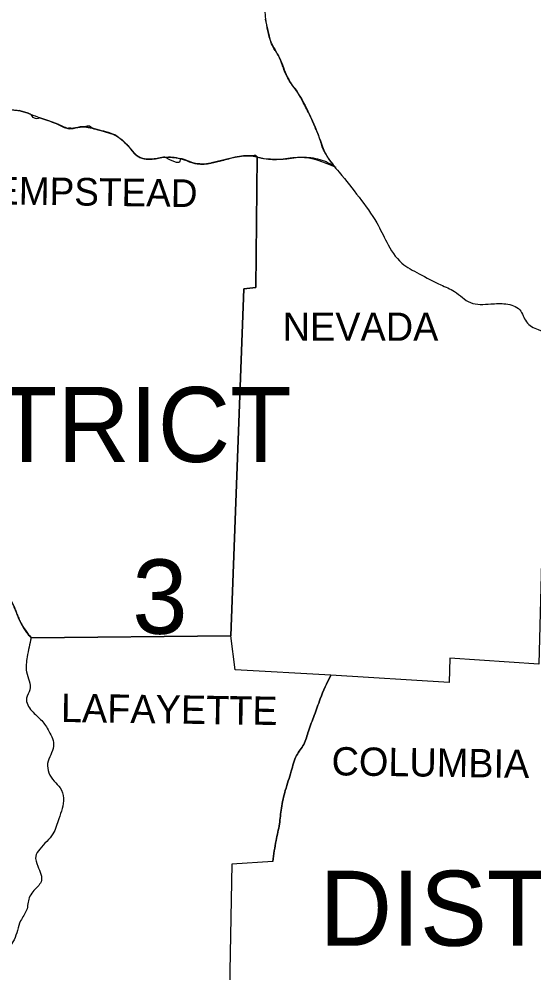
# Model space of a CAD drawing. Extents: x -12863 to 18921, y -8840 to 11152.
# Drawn here: x 11783 to 12548, y 5265 to 6683 of the extents above; entities that cross this region are included whole.
import ezdxf

# ---------------------------------------------------------------- set-up
doc = ezdxf.new("R2010")
doc.units = 0
for name, color, linetype in [('Level 1', 7, 'Continuous'), ('Level 2', 7, 'Continuous'), ('Level 3', 7, 'Continuous'), ('Level 48', 7, 'Continuous')]:
    doc.layers.add(name, color=color, linetype=linetype)

msp = doc.modelspace()

# ---------------------------------------------------------------- linework, layer by layer
at = {"layer": 'Level 1'}
for points in [[(12136.685074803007, 6478.611953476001), (12134.728261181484, 6283.908996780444), (12117.116938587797, 6281.952183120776), (12097.548802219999, 5766.331790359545)], [(12568.162481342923, 6217.377333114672), (12555.443192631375, 5724.260297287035), (12423.358272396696, 5733.06595852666), (12422.379865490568, 5696.86490635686), (12246.266638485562, 5707.62738140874)], [(12246.266638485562, 5707.62738140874), (12104.397649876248, 5715.454635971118), (12097.548802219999, 5766.331790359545), (11801.09153644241, 5763.396570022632)], [(12160.166838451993, 5430.73825199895), (12099.50561584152, 5426.824624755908), (12092.656768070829, 5082.425425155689)]]:
    msp.add_lwpolyline(points, dxfattribs=at)
for points in [[(12084.829513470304, 6880.7371554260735), (12100.48402259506, 6870.953087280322), (12119.073752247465, 6862.147425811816), (12128.857820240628, 6847.471323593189), (12132.771447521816, 6824.967966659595), (12139.620295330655, 6800.507796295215), (12141.577108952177, 6775.069219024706), (12135.706668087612, 6761.371523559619), (12143.533922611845, 6730.062505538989), (12146.469142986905, 6708.537555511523), (12149.404363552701, 6683.098978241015), (12157.231618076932, 6648.854739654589), (12169.950906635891, 6625.37297604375), (12181.691788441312, 6596.9991783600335), (12201.25992480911, 6566.668566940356), (12217.892840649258, 6533.402735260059), (12225.720095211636, 6515.791412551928), (12240.396197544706, 6479.590360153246), (12258.985927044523, 6455.130189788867), (12288.33813159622, 6417.950730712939), (12314.755115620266, 6379.792864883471), (12329.431217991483, 6351.419067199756), (12351.934574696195, 6320.110048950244), (12377.37315200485, 6304.455539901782), (12409.660576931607, 6287.82262409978), (12430.207120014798, 6278.038555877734), (12453.688883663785, 6261.405640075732), (12484.019494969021, 6259.448826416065), (12506.522851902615, 6259.448826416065), (12527.069394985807, 6250.643164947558), (12536.853463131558, 6233.031842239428), (12554.464785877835, 6221.2909603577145), (12568.162481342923, 6217.377333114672)], [(11684.224975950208, 6556.249495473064), (11725.754211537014, 6552.970871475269), (11759.998450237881, 6549.0572441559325), (11786.41543426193, 6546.122023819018), (11813.810825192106, 6536.337955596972), (11838.270995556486, 6527.532294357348), (11853.925504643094, 6520.683446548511), (11880.342488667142, 6522.640260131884), (11902.845845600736, 6517.748226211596), (11928.284422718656, 6508.942564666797), (11946.874152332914, 6492.309648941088), (11958.61503417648, 6479.590360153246), (11981.118390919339, 6474.698326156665), (11999.708120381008, 6477.633546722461), (12022.211477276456, 6475.676733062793), (12047.650054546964, 6467.849478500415), (12068.196597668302, 6468.827885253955), (12084.829513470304, 6472.741512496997), (12104.397649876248, 6477.633546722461), (12128.857820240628, 6479.590360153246), (12147.447549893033, 6475.676733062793), (12171.907720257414, 6474.698326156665), (12200.281517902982, 6477.633546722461), (12253.57048874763, 6462.8310547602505)], [(11400.923148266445, 5874.934947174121), (11435.167386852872, 5889.611049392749), (11449.843489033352, 5884.719015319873), (11462.5627777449, 5871.999726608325), (11477.238879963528, 5871.999726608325), (11485.066134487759, 5883.740608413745), (11499.742236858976, 5884.719015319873), (11511.483118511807, 5883.740608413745), (11524.202407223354, 5891.567862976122), (11534.964882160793, 5896.459897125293), (11549.64098453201, 5901.351931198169), (11560.403459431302, 5905.2655584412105), (11570.1875276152, 5916.028033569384), (11587.798850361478, 5924.833694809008), (11608.345393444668, 5931.682542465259), (11614.215834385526, 5941.466610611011), (11623.999902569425, 5945.380237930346), (11643.568038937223, 5944.401831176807), (11656.287327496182, 5950.272272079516), (11667.049802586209, 5945.380237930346), (11676.833870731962, 5938.531390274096), (11678.79068439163, 5913.092813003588), (11686.617938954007, 5899.395117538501), (11698.358820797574, 5874.934947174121), (11714.99173656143, 5862.215658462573), (11730.646245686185, 5849.496369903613), (11736.516686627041, 5841.669115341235), (11753.14960246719, 5826.993013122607), (11767.82570480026, 5822.100978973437), (11774.67455245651, 5811.338503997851), (11785.437027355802, 5785.899926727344), (11801.09153644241, 5763.396570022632)], [(11801.09153644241, 5763.396570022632), (11795.221095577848, 5735.0227721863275), (11794.242688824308, 5712.519415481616), (11799.134722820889, 5686.102431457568), (11794.242688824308, 5673.38314274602), (11802.069943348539, 5654.793413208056), (11816.746045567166, 5640.117311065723), (11827.508520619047, 5624.4628019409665), (11834.357368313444, 5601.959445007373), (11825.551706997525, 5576.520867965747), (11835.335775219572, 5550.103883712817), (11844.141436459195, 5540.319815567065), (11849.033470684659, 5524.665306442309), (11842.184622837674, 5494.334695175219), (11833.378961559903, 5471.831338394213), (11813.810825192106, 5449.327981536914), (11807.940384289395, 5438.565506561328), (11810.87560462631, 5423.889404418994), (11815.767638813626, 5400.40764073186), (11810.87560462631, 5393.558792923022), (11798.156316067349, 5376.92587712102), (11794.242688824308, 5358.33614765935), (11785.437027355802, 5342.681638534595), (11775.652959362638, 5314.30784069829), (11762.933670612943, 5290.826077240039), (11760.976856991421, 5264.409093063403), (11741.408720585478, 5264.409093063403), (11718.905363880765, 5264.409093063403), (11698.358820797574, 5249.7329908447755), (11679.76909114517, 5248.754583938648), (11657.26573440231, 5239.948922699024), (11643.568038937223, 5221.359193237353), (11638.676004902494, 5200.812649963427), (11632.805563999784, 5181.2445135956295), (11638.676004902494, 5147.978681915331), (11647.481666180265, 5124.496918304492), (11654.330513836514, 5105.90718861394), (11666.071395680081, 5075.57657734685)], [(12160.166838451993, 5430.73825199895), (12165.05887263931, 5462.047270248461), (12169.950906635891, 5486.5074406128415), (12172.886127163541, 5509.989204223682), (12178.756568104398, 5536.406188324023), (12187.562229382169, 5564.779986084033), (12195.3894839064, 5588.2617496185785), (12206.15195880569, 5604.894665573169), (12213.000806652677, 5624.4628019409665), (12221.806467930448, 5647.944565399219), (12230.612129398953, 5672.40473599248), (12246.266638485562, 5707.62738140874)]]:
    msp.add_spline(points, degree=3, dxfattribs=at)
at = {"layer": 'Level 48'}
for p, q in [((12157.231618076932, 6648.854739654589), (12149.430175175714, 6682.890797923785)), ((11786.41543426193, 6546.122023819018), (11783.151815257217, 6546.813521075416)), ((11788.004384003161, 6545.716124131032), (11786.415434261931, 6546.122023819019)), ((11793.416260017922, 6544.079103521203), (11788.004384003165, 6545.716124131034)), ((11827.192270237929, 6531.523843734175), (11813.810825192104, 6536.337955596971)), ((11838.270995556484, 6527.532294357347), (11827.192270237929, 6531.523843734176)), ((11840.671905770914, 6526.582323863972), (11838.270995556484, 6527.532294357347)), ((11842.207581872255, 6525.900785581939), (11840.671905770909, 6526.5823238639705)), ((11849.923944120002, 6522.24184290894), (11846.05493396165, 6524.059128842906)), ((11877.58567751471, 6522.846575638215), (11873.746675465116, 6522.525669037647)), ((11880.342488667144, 6522.640260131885), (11877.58567751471, 6522.846575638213)), ((11867.061234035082, 6521.133758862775), (11860.412173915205, 6520.005895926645)), ((11902.845845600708, 6517.748226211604), (11891.619067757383, 6520.505593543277)), ((11915.693227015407, 6514.32547525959), (11908.949037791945, 6516.1663243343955)), ((11915.881764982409, 6514.272311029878), (11915.693227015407, 6514.32547525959)), ((11920.119255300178, 6512.85322364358), (11915.881764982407, 6514.272311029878)), ((11923.811730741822, 6511.325090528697), (11922.207173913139, 6512.02970897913)), ((11925.282433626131, 6510.615522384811), (11923.811730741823, 6511.325090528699)), ((11928.284422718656, 6508.942564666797), (11925.282433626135, 6510.615522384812)), ((11938.083539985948, 6501.103951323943), (11928.284422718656, 6508.942564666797)), ((11946.874152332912, 6492.309648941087), (11938.08353998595, 6501.103951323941)), ((11951.293284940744, 6487.122491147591), (11949.69766156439, 6489.164088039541)), ((11952.27300157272, 6485.863031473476), (11951.293284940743, 6487.122491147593)), ((11958.61503417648, 6479.590360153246), (11952.273001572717, 6485.863031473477)), ((12116.589936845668, 6479.522672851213), (12104.397649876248, 6477.633546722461)), ((12120.822924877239, 6479.738221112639), (12116.589936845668, 6479.5226728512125)), ((12128.857820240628, 6479.590360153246), (12122.752286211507, 6479.7681118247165)), ((11964.83291060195, 6476.395905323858), (11964.097617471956, 6476.667742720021)), ((11969.719617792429, 6475.1508068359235), (11964.832910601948, 6476.395905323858)), ((11975.189498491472, 6474.637350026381), (11969.719617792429, 6475.150806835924)), ((11981.118390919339, 6474.698326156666), (11975.189498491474, 6474.637350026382)), ((11983.913866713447, 6474.957334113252), (11981.118390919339, 6474.698326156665)), ((11985.763499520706, 6475.259851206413), (11983.913866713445, 6474.957334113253)), ((11990.408432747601, 6476.256197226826), (11985.763499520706, 6475.259851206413)), ((11995.055777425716, 6477.207412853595), (11990.408432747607, 6476.256197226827)), ((11997.795583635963, 6477.552759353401), (11995.055777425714, 6477.207412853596)), ((11999.708120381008, 6477.633546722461), (11997.79558363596, 6477.552759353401)), ((12025.463872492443, 6474.942097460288), (12022.211477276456, 6475.676733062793)), ((12028.6646643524, 6473.946619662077), (12025.463872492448, 6474.942097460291)), ((12034.955247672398, 6471.560421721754), (12028.664664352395, 6473.946619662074)), ((12041.233590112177, 6469.275565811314), (12034.955247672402, 6471.560421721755)), ((12045.519318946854, 6468.176389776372), (12041.23359011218, 6469.275565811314)), ((12047.650054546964, 6467.849478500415), (12045.519318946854, 6468.17638977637)), ((12068.196597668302, 6468.827885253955), (12057.941363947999, 6467.4799135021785)), ((12136.680049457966, 6478.111931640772), (12136.559396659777, 6478.144430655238)), ((12136.685074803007, 6478.611953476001), (12136.680049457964, 6478.11193164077)), ((11801.09153644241, 5763.396570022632), (12097.548802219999, 5766.331790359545))]:
    msp.add_line(p, q, dxfattribs=at)
for points in [[(12097.548802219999, 5766.331790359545), (12117.116938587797, 6281.952183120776), (12134.728261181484, 6283.908996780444), (12136.680049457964, 6478.111931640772)], [(12136.559396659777, 6478.144430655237), (12136.685074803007, 6478.611953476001)], [(12555.346192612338, 5724.266763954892), (12423.358272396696, 5733.06595852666), (12422.379865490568, 5696.86490635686), (12246.266638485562, 5707.62738140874)], [(12160.16683845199, 5430.738251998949), (12099.50561584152, 5426.824624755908), (12092.656768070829, 5082.425425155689)]]:
    msp.add_lwpolyline(points, dxfattribs=at)
for points in [[(12084.829513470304, 6880.7371554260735), (12100.48402259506, 6870.953087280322), (12119.073752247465, 6862.147425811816), (12128.857820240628, 6847.471323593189), (12132.771447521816, 6824.967966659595), (12139.620295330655, 6800.507796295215), (12141.577108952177, 6775.069219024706), (12135.706668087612, 6761.371523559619), (12143.533922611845, 6730.062505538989), (12146.469142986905, 6708.537555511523), (12149.404363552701, 6683.098978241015), (12157.231618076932, 6648.854739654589), (12169.950906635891, 6625.37297604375), (12181.691788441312, 6596.9991783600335), (12201.25992480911, 6566.668566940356), (12217.892840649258, 6533.402735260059), (12225.720095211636, 6515.791412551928), (12240.396197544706, 6479.590360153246), (12258.985927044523, 6455.130189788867), (12288.33813159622, 6417.950730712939), (12314.755115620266, 6379.792864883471), (12329.431217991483, 6351.419067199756), (12351.934574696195, 6320.110048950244), (12377.37315200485, 6304.455539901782), (12409.660576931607, 6287.82262409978), (12430.207120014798, 6278.038555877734), (12453.688883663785, 6261.405640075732), (12484.019494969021, 6259.448826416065), (12506.522851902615, 6259.448826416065), (12527.069394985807, 6250.643164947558), (12536.853463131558, 6233.031842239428), (12554.464785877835, 6221.2909603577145), (12568.162481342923, 6217.377333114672)], [(11684.240166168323, 6556.248841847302), (11725.754211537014, 6552.970871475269), (11759.998450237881, 6549.0572441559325), (11773.25629404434, 6548.0059087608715), (11779.86753077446, 6547.330862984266), (11783.151815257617, 6546.8135210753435), (11786.41543426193, 6546.122023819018), (11793.416260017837, 6544.079103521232), (11800.2496263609, 6541.592829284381), (11813.810825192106, 6536.337955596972), (11838.270995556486, 6527.532294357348), (11842.207581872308, 6525.900785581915), (11846.054933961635, 6524.059128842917), (11849.923944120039, 6522.241842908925), (11853.925504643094, 6520.683446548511), (11860.412173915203, 6520.005895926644), (11867.061234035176, 6521.133758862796), (11873.746675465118, 6522.525669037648), (11880.342488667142, 6522.640260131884), (11891.619067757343, 6520.505593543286), (11902.845845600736, 6517.748226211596), (11915.881764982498, 6514.272311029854), (11922.20717391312, 6512.029708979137), (11925.282433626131, 6510.615522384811), (11928.284422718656, 6508.942564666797), (11938.083539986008, 6501.103951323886), (11946.874152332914, 6492.309648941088), (11949.697661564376, 6489.164088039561), (11952.273001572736, 6485.863031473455), (11958.61503417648, 6479.590360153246), (11964.097617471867, 6476.667742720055), (11969.71961779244, 6475.150806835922), (11981.118390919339, 6474.698326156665), (11985.763499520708, 6475.259851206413), (11990.408432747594, 6476.256197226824), (11995.055777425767, 6477.207412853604), (11999.708120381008, 6477.633546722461), (12022.211477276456, 6475.676733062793), (12028.664664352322, 6473.946619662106), (12034.955247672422, 6471.560421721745), (12041.233590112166, 6469.275565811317), (12047.650054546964, 6467.849478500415), (12052.76136923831, 6467.464625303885), (12057.941363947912, 6467.479913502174), (12068.196597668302, 6468.827885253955), (12084.829513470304, 6472.741512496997), (12104.397649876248, 6477.633546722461), (12116.589936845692, 6479.522672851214), (12122.752286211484, 6479.7681118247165), (12128.857820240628, 6479.590360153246), (12136.559396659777, 6478.144430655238)], [(11800.249626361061, 6541.592829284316), (11800.2496263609, 6541.592829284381), (11793.41626001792, 6544.079103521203)], [(11813.810825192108, 6536.337955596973), (11813.810825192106, 6536.337955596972), (11800.249626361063, 6541.592829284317)], [(11846.054933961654, 6524.05912884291), (11846.054933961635, 6524.059128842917), (11842.207581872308, 6525.900785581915), (11842.207581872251, 6525.900785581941)], [(11853.925504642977, 6520.683446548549), (11849.923944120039, 6522.241842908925), (11849.92394412, 6522.241842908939)], [(11873.74667546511, 6522.525669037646), (11867.061234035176, 6521.133758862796), (11867.061234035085, 6521.133758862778)], [(11891.61906775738, 6520.5055935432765), (11880.342488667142, 6522.640260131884), (11880.34248866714, 6522.640260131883)], [(11854.710488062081, 6520.450682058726), (11853.925504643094, 6520.683446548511), (11853.925504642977, 6520.68344654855)], [(11860.412173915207, 6520.005895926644), (11860.412173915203, 6520.005895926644), (11854.710488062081, 6520.450682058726)], [(11908.949037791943, 6516.1663243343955), (11902.845845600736, 6517.748226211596), (11902.845845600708, 6517.748226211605)], [(11922.207173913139, 6512.029708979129), (11922.20717391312, 6512.029708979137), (11920.11925530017, 6512.8532236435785)], [(11949.697661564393, 6489.164088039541), (11949.697661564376, 6489.164088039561), (11946.874152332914, 6492.309648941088)], [(11964.097617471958, 6476.667742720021), (11964.097617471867, 6476.667742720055), (11958.61503417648, 6479.590360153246)], [(12122.752286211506, 6479.7681118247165), (12122.752286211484, 6479.7681118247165), (12120.82292487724, 6479.738221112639)], [(12136.559396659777, 6478.144430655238), (12128.857820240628, 6479.590360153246), (12128.857820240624, 6479.590360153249)], [(12022.211477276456, 6475.676733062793), (11999.708120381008, 6477.633546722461), (11999.70812038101, 6477.633546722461)], [(12136.680049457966, 6478.111931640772), (12142.032311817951, 6476.664765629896), (12147.447549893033, 6475.676733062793), (12159.670621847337, 6474.882897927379), (12171.907720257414, 6474.698326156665), (12179.012567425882, 6475.141780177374), (12186.105670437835, 6476.095226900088), (12193.193247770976, 6477.084028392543), (12200.281517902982, 6477.633546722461), (12213.505043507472, 6477.266756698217), (12226.593825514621, 6475.211607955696), (12239.385293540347, 6470.997306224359), (12251.716877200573, 6464.15305723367)], [(11401.970630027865, 5875.762733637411), (11410.038158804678, 5881.300332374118), (11418.321702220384, 5885.515487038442), (11426.728898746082, 5888.316343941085), (11430.950003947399, 5889.1577064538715), (11435.167386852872, 5889.611049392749), (11438.82118587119, 5889.341318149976), (11442.520433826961, 5888.264884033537), (11446.212183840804, 5886.638524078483), (11449.843489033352, 5884.719015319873), (11453.491548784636, 5881.84193745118), (11456.464932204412, 5878.289693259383), (11459.30741621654, 5874.772287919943), (11462.5627777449, 5871.999726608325), (11469.87758880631, 5870.38422223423), (11473.804964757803, 5870.8442190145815), (11477.238879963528, 5871.999726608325), (11479.435402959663, 5874.5058688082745), (11480.846005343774, 5878.25179409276), (11482.409858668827, 5881.806906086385), (11485.066134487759, 5883.740608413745), (11488.73326028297, 5884.283980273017), (11492.403641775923, 5884.597624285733), (11496.074295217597, 5884.727362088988), (11499.742236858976, 5884.719015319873), (11502.67961757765, 5884.3910291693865), (11505.617538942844, 5883.812605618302), (11510.018935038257, 5883.479551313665), (11510.751265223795, 5883.578457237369), (11511.483118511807, 5883.740608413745), (11514.928437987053, 5885.222733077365), (11518.020976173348, 5887.350551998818), (11521.024407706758, 5889.630212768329), (11524.202407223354, 5891.567862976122), (11526.8541714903, 5892.860173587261), (11529.516322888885, 5894.153550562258), (11534.964882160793, 5896.459897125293), (11549.64098453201, 5901.351931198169), (11560.403459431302, 5905.2655584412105), (11563.249118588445, 5907.3571858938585), (11565.427322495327, 5910.381345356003), (11567.539611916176, 5913.538230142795), (11570.1875276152, 5916.028033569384), (11578.855900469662, 5920.722356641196), (11587.798850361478, 5924.833694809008), (11592.877181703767, 5926.688179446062), (11598.111097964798, 5928.177223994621), (11603.325526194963, 5929.706715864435), (11608.345393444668, 5931.682542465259), (11610.238379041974, 5933.590616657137), (11611.31993120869, 5936.356302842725), (11612.381824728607, 5939.2311258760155), (11614.215834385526, 5941.466610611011), (11616.547921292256, 5942.866234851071), (11618.955985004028, 5943.986147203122), (11623.999902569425, 5945.380237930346), (11628.937732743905, 5945.560966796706), (11633.968008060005, 5945.0118671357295), (11638.906264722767, 5944.402351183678), (11643.568038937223, 5944.401831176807), (11646.752995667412, 5945.663915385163), (11649.930844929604, 5947.879706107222), (11653.107113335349, 5949.824169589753), (11656.287327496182, 5950.272272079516), (11661.667218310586, 5948.295230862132), (11667.049802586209, 5945.380237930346), (11672.27531092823, 5942.386166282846), (11674.661302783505, 5940.6674813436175), (11675.777182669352, 5939.664250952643), (11676.833870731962, 5938.531390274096), (11679.049497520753, 5932.707550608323), (11678.525243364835, 5926.034450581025), (11677.644506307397, 5919.250176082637), (11678.79068439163, 5913.092813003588), (11680.699467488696, 5909.655069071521), (11682.706384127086, 5906.245452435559), (11684.712264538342, 5902.835092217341), (11686.617938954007, 5899.395117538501), (11689.308010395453, 5893.147772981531), (11691.635519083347, 5886.65524926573), (11696.172899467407, 5877.550657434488), (11697.20938611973, 5876.207489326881), (11698.358820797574, 5874.934947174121), (11702.291174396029, 5871.414373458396), (11706.49590851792, 5868.298034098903), (11710.790327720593, 5865.32032909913), (11714.99173656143, 5862.215658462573), (11722.882252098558, 5855.938539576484), (11730.646245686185, 5849.496369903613), (11732.29759060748, 5847.718360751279), (11733.687404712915, 5845.70455215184), (11735.024249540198, 5843.629838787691), (11736.516686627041, 5841.669115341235), (11744.465728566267, 5833.874596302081), (11748.743274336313, 5830.341582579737), (11753.14960246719, 5826.993013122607), (11756.673031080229, 5825.487299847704), (11760.663262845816, 5824.851298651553), (11764.565690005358, 5824.0631461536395), (11766.310661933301, 5823.292680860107), (11767.82570480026, 5822.100978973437), (11771.692481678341, 5816.977172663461), (11774.67455245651, 5811.338503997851), (11777.478317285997, 5805.012819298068), (11780.04657591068, 5798.624648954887), (11782.619441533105, 5792.23376181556), (11785.437027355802, 5785.899926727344), (11788.535932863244, 5779.82862433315), (11792.008155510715, 5774.072396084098), (11796.10844135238, 5768.604093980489), (11798.473716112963, 5765.969431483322), (11801.09153644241, 5763.396570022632)], [(12246.266638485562, 5707.62738140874), (12230.612129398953, 5672.40473599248), (12221.806467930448, 5647.944565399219), (12213.000806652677, 5624.4628019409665), (12206.15195880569, 5604.894665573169), (12195.3894839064, 5588.2617496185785), (12187.562229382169, 5564.779986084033), (12178.756568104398, 5536.406188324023), (12172.886127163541, 5509.989204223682), (12169.950906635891, 5486.5074406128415), (12165.05887263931, 5462.047270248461), (12160.166838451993, 5430.73825199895)]]:
    msp.add_spline(points, degree=3, dxfattribs=at)
for points, degree in [([(12181.691788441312, 6596.9991783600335), (12176.96471033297, 6606.0694115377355), (12174.23627494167, 6616.12881380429), (12169.950906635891, 6625.37297604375), (12166.22400291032, 6633.412449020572), (12160.422905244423, 6640.426176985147), (12157.231618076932, 6648.854739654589)], 3), ([(12217.892840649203, 6533.402735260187), (12212.734125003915, 6544.685333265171), (12207.044868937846, 6555.706124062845), (12201.25992480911, 6566.668566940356), (12195.6456416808, 6577.30760799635), (12187.248319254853, 6586.3374061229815), (12181.691788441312, 6596.9991783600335), (12181.691788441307, 6596.9991783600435), (12181.691788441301, 6596.999178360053), (12181.691788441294, 6596.999178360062)], 3), ([(12227.87013113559, 6510.475942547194), (12227.196538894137, 6512.266966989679), (12226.487306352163, 6514.042122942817), (12225.720095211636, 6515.791412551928), (12223.140703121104, 6521.67258859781), (12220.565991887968, 6527.556301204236), (12217.892840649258, 6533.402735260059)], 3), ([(12240.396197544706, 6479.590360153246), (12234.498346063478, 6489.111822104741), (12231.78669903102, 6500.0621218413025), (12227.87013113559, 6510.475942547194)], 2), ([(12251.716877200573, 6464.15305723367), (12247.709244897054, 6469.107954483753), (12243.781622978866, 6474.124946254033), (12240.396197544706, 6479.590360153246)], 2), ([(12057.941363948, 6467.479913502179), (12057.941363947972, 6467.479913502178), (12057.94136394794, 6467.479913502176), (12057.941363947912, 6467.479913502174), (12056.216686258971, 6467.377723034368), (12054.486629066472, 6467.4059826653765), (12052.76136923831, 6467.464625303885), (12051.054172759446, 6467.522653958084), (12049.351252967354, 6467.628036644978), (12047.650054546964, 6467.849478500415)], 3), ([(12084.829513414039, 6472.741512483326), (12079.294531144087, 6471.396634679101), (12073.76944445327, 6470.078557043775), (12068.196597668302, 6468.827885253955)], 2), ([(12104.397649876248, 6477.633546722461), (12097.847674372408, 6476.052231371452), (12091.363492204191, 6474.329282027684), (12084.829513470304, 6472.741512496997), (12084.82951345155, 6472.74151249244), (12084.829513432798, 6472.741512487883), (12084.829513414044, 6472.741512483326)], 3)]:
    msp.add_open_spline(points, degree=degree, dxfattribs=at)

# ---------------------------------------------------------------- texts
at = {"layer": 'Level 2'}
for s, height, rotation, p in [('HEMPSTEAD', 41.08134544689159, 359.1885000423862, (11706.186075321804, 6408.166662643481)), ('LAFAYETTE', 42.06170907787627, 359.18387503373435, (11845.119843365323, 5638.160497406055)), ('COLUMBIA', 42.06170907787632, 359.212477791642, (12247.245045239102, 5558.909545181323))]:
    msp.add_text(s, height=height, rotation=rotation, dxfattribs=at).set_placement(p)
msp.add_text('NEVADA', height=42.07344995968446, dxfattribs=at).set_placement((12174.84294082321, 6204.658044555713))
at = {"layer": 'Level 3'}
for s, height, p in [('DISTRICT', 111.53837717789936, (11500.22631536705, 6024.518902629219)), ('3', 110.55801354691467, (11951.271858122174, 5769.189795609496)), ('DISTRICT 7', 111.53837717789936, (12229.633722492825, 5305.502179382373))]:
    msp.add_text(s, height=height, dxfattribs=at).set_placement(p)

doc.saveas('drawing.dxf')
